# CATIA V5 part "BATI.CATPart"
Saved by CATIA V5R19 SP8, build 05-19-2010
Part number: BATI
Bounding box of the stored display mesh (mm): x -28.549 to 5.549, y -27.049 to 27.049, z -31 to 22
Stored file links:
  C:\Users\ThinkMotion\Desktop\EU_thinkMotion\iao\IAO_MMS_Groupe3\jbuffard\jbuffard\BATI.CATPart
  C:\Users\ThinkMotion\Desktop\EU_thinkMotion\iao\IAO_MMS_Groupe3\jbuffard\jbuffard\Mecanisme a coulisse a quatre elements de la griffe d'une camera.CATProduct
  C:\Users\ThinkMotion\Desktop\EU_thinkMotion\iao\IAO_MMS_Groupe3\jbuffard\jbuffard\Squelette de base.CATPart
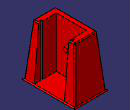
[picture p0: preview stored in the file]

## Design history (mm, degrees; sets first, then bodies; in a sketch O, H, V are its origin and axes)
External parameters (linked from other documents)
  `External.Largeur bati` = 0.043
  `External.Demi-largeur bati` = 0.0215
  External.Largeur = 0.031
  `External.Demi-largeur` = 0.0155
Set1
  Plane1 to Plane4: linked copy from another document
  Point1: linked copy from another document
  Plane5: linked copy from another document
  Plane6: linked copy from another document
  Point2: linked copy from another document
Body1 (main body)
  Sketch1 on Plane1, origin (0, 0, 22), H (1, 0, 0), V (0, 1, 0)
    line L1 (-23, 21.5) -> (0, 21.5)
    line L2 (0, 21.5) -> (0, -21.5)
    line L3 (0, -21.5) -> (-23, -21.5)
    line L4 (-23, -21.5) -> (-23, 21.5)
    length L2 = 43 {= `External.Largeur bati`}
    length L1 = 23
    distance H L1 = 21.5 {= `External.Demi-largeur bati`}
    horizontal: L1 H, L3 H
    vertical: L2 V, L4 V
    coincidence: L2 V
  Pad1: profile Sketch1, direction (0, 0, -1), length 0, opposite side up to Plane2
  Draft1: PullDir end face of Pad1, Angle -5, SupportToDraft (face of Pad1 from Sketch1.L1; face of Pad1 from Sketch1.L2; face of Pad1 from Sketch1.L3; face of Pad1 from Sketch1.L4), Neutral end face of Pad1
  Fillet1: radius 1, on edge [face of Pad1 from Sketch1.L2 | face of Pad1 from Sketch1.L1]; edge [face of Pad1 from Sketch1.L3 | face of Pad1 from Sketch1.L2]; edge [face of Pad1 from Sketch1.L4 | face of Pad1 from Sketch1.L3]; edge [face of Pad1 from Sketch1.L1 | face of Pad1 from Sketch1.L4]
  Fillet2: radius 1, on edge [face of Pad1 from Sketch1.L1 | end face of Pad1]; edge [face of Pad1 from Sketch1.L2 | end face of Pad1]; edge [face of Pad1 from Sketch1.L3 | end face of Pad1]; edge [face of Pad1 from Sketch1.L4 | end face of Pad1]
  Sketch2 on Plane3, origin (0, 0, -30), H (1, 0, 0), V (0, 1, 0)
    line L1 (-4, 17.5) -> (-4, 15.5)
    line L2 (-4, 15.5) -> (-18, 15.5)
    line L3 (-18, 15.5) -> (-18, -15.5)
    line L4 (-18, -15.5) -> (-4, -15.5)
    point P5 (-4, -15.5)
    line L5 (-4, -15.5) -> (-4, -17.5)
    line L6 (-4, -17.5) -> (-2, -17.5)
    line L7 (-2, -17.5) -> (-2, -15.5)
    point P8 (-2, -15.5)
    line L8 (-2, -15.5) -> (9.8355, -15.5)
    line L9 (9.8355, -15.5) -> (9.8355, 15.5)
    point P10 (9.8355, 15.5)
    line L10 (9.8355, 15.5) -> (-2, 15.5)
    point P11 (-2, 15.5)
    line L11 (-2, 15.5) -> (-2, 17.5)
    line L12 (-2, 17.5) -> (-4, 17.5)
    length L12 = 2
    distance L1 L3 = 14
    distance L4 L2 = 31 {= External.Largeur}
    length L11 = 2
    length L7 = 2
    distance V L3 = 18
    distance L2 H = 15.5 {= `External.Demi-largeur`}
    vertical: L1 V, L3 V, L5 V, L7 V, L9 V, L11 V
    horizontal: L2 H, L4 H, L6 H, L8 H, L10 H, L12 H
    coincidence: P5 L1, P8 L4, P10 L2, P11 L7
  Pocket1: profile Sketch2, direction (0, 0, 1), up to Plane1
  Sketch3 on Plane3, origin (0, 0, -30), H (1, 0, 0), V (0, 1, 0)
    line L1 (-28.5494, 27.0494) -> (5.5494, 27.0494)
    line L2 (5.5494, 27.0494) -> (5.5494, -27.0494)
    line L3 (5.5494, -27.0494) -> (-28.5494, -27.0494)
    line L4 (-28.5494, -27.0494) -> (-28.5494, 27.0494)
    reference projected line E1 (-27.5494, 26.0494) -> (4.5494, 26.0494) from edge [face of Pad1 from Sketch1.L1 | start face of Pad1]
    reference projected line E2 (4.5494, -26.0494) -> (-27.5494, -26.0494) from edge [face of Pad1 from Sketch1.L3 | start face of Pad1]
    reference projected line E3 (-27.5494, -26.0494) -> (-27.5494, 26.0494) from edge [face of Pad1 from Sketch1.L4 | start face of Pad1]
    reference projected line E4 (4.5494, 26.0494) -> (4.5494, -26.0494) from edge [face of Pad1 from Sketch1.L2 | start face of Pad1]
    distance E1 L1 = 1
    distance L3 E2 = 1
    distance L4 E3 = 1
    distance E4 L2 = 1
    horizontal: L1 H, L3 H
    vertical: L2 V, L4 V
  Pad2: profile Sketch3, direction (0, 0, -1), length 1
  Fillet3: radius 1, on edge [face of Pad2 from Sketch3.L2 | start face of Pad2]; edge [face of Pad2 from Sketch3.L3 | start face of Pad2]; edge [face of Pad2 from Sketch3.L4 | start face of Pad2]; edge [face of Pad2 from Sketch3.L1 | start face of Pad2]
  Sketch4 on Plane4, origin (-18, 0, 0), H (0, 1, 0), V (0, 0, 1)
    circle A1 centre (0, 0) radius 3.5
    point P1 (0, 0)
    reference projected point E1 (0, 0) from Point2
    radius A1 = 3.5
    coincidence: P1 E1
  Pad3: profile Sketch4, direction (1, 0, 0), up to Plane5
  Sketch5 on Plane5, origin (-17, 0, 0), H (0, 1, 0), V (0, 0, 1)
    circle A1 centre (0, 0) radius 2.5
    reference projected circle E1 centre (0, 0) radius 3.5 from edge [face of Pad3 from Sketch4.A1 | end face of Pad3]
    radius A1 = 2.5
    concentricity: A1 E1
  Pad4: profile Sketch5, direction (1, 0, 0), up to Plane6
